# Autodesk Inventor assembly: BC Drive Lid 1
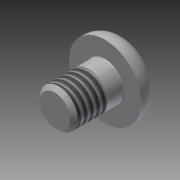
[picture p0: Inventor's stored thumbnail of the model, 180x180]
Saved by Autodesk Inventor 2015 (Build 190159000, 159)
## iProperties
Created: 2007-02
Part Number: BC Drive Lid 1
Document SubType Name: Assembly
Designer: Autodesk, Inc.
Mass: 1.89148 g
Surface Area: 2.92112 cm^2
Volume: 0.240646 cm^3
Density: 7.86 g/cm^3
ClientObjectVersion: 1
Author: Autodesk, Inc.
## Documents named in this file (2)
- C:\Users\Public\Documents\Autodesk\Inventor 2015\Samples\Models\Assemblies\Blower\Blower\Design Accelerator\BC Motor Mount 41.iam
- C:\Users\Public\Documents\Autodesk\Inventor 2015\Samples\Standard Parts\en-US\ANSI B18.3(03)\ANSI B18.3 - 10-32 UNF - UNF - 0.25(1).ipt
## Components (1 placed, 1 different names)
1. ANSI B18.3 - No. 10-32 - 1/4:1
